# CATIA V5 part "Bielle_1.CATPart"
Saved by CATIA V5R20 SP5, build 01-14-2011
Part number: Bielle_1
Publications: "Droite.1", "Droite.2", "Droite.3", "Droite.4"
Bounding box of the stored display mesh (mm): x 0 to 200, y 0 to 0, z -900 to 0
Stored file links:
  J:\Thinkmotion\Projet IAO\A envoyer\Bielle_1.CATPart
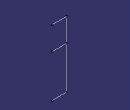
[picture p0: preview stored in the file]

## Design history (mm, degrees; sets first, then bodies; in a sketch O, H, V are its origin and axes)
Set1
  Line1: type PtPt, FirstPoint Point1, SecondPoint Point12
  Point1 "A": stored without definition
  Point2 "I": stored without definition
  Line2: type Normal, RefPoint Point3, RefSkin yz-plane, Start 0, End 200
  Point3 "A": stored without definition
  Line3: type Normal, RefPoint Point11, RefSkin yz-plane, Start 0, End 200
  Point4 "I": stored without definition
  Line4: type Normal, RefPoint Point6, RefSkin yz-plane, Start 0, End 200
  Point5 "B": stored without definition
  Point6 "B": stored without definition
  Point7 to Point12 "I": stored without definition
Body1 (main body)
